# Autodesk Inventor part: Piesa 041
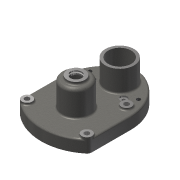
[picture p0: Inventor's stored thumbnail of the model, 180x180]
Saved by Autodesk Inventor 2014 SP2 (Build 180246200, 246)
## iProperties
Created: 2009-01
Part Number: Piesa 041
Document SubType Name: Modeling
Designer: Costel
Material: Steel, Cast
Density: 7.85 g/cm^3
Appearance: Steel - Cast
Author: Costel
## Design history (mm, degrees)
sketch "Sketch1"
  geometry: L1 (0, -196.304)-(0, 82.999) reference; L2 (-114.665, 0)-(114.665, 0) reference; L3 (-69.5, -125)-(-69.5, -47.789); L4 (69.5, -125)-(69.5, -47.789); A1 r 38 centre (0, 0) between (14.981, 34.922) and (-14.981, 34.922); A2 r 103.404 centre (0, -53) between (-65.87, -132.708) and (65.87, -132.708); A3 r 90 centre (20.5, -47.789) between (-14.981, 34.922) and (-69.5, -47.789); A4 r 90 centre (-20.5, -47.789) between (69.5, -47.789) and (14.981, 34.922); A5 r 10 centre (-59.5, -125) between (-69.5, -125) and (-65.87, -132.708); A6 r 10 centre (59.5, -125) between (65.87, -132.708) and (69.5, -125)
  constraints: 12 point on circle, 6 centre point, 6 tangent, 4 end point, 3 symmetric about line, 2 parallel, 2 point on line, 1 equal radius, 1 midpoint, 2 other
  dimensions: "d0" = 76 diameter of A1; "d1" = 53 distance of A1.centre A2.centre; "d5" = 139 distance between parallel lines of L4 L3; "d6" = 10 radius of A5; "d7" = 90 radius of A3; "d87" = 125 vertical distance of A5.centre A1.centre
extrude "Extrusion1" new body sketch "Sketch1" distance "d8" = 24; taper "d9" = 0 deg
sketch "Sketch2"
  geometry: L1 (0, -187)-(0, 75.5) reference; A1 r 38 centre (0, 0) between (14.981, 34.922) and (-14.981, 34.922) reference; A2 r 32 centre (0, 0) between (24.222, -20.911) and (-24.222, -20.911); A3 r 62.5 centre (0, -87) between (-26.245, -30.277) and (26.245, -30.277); A4 r 6 centre (-28.764, -24.832) between (-26.245, -30.277) and (-24.222, -20.911); A5 r 6 centre (28.764, -24.832) between (24.222, -20.911) and (26.245, -30.277)
  constraints: 8 point on circle, 4 centre point, 4 tangent, 1 coincident, 1 equal radius, 1 point on line
  dimensions: "d10" = 64 diameter of A2; "d11" = 87 distance of A1.centre A3.centre; "d12" = 125 diameter of A3; "d13" = 6 radius of A4
extrude "Extrusion2" cut sketch "Sketch2" distance "d14" = 18; taper "d15" = 0 deg
sketch "Sketch3"
  geometry: L1 (0, -195.284)-(0, 76.881) reference; L2 (-142.964, 0)-(175.456, 0) reference; L3 (-97.476, -11)-(129.968, -11); 2 further points
  constraints: 2 end point, 1 parallel, 1 point on line, 1 symmetric about line
  dimensions: "d16" = 11 distance between parallel lines of L2 L3; "d17" = 97 distance of point (48.5, -11) point (-48.5, -11)
hole "Hole1" sketch "Sketch3" at (-48.5, -11), (48.5, -11) diameter "d18" = 7.647; stored, may be unused: countersink angle "d22" = 90 deg, drill point angle "d24" = 118 deg; dims "d19" = 6, "d20" = 4, "d21" = 2, "d23" = 8
sketch "Sketch4"
  geometry: L1 (-142.964, 0)-(175.456, 0) reference; L2 (0, -195.284)-(0, 76.881) reference; L3 (-97.476, -24)-(129.968, -24); 2 further points
  constraints: 2 end point, 1 parallel, 1 point on line, 1 symmetric about line
  dimensions: "d25" = 24 distance between parallel lines of L1 L3; "d26" = 64 distance of point (32, -24) point (-32, -24)
hole "Hole2" sketch "Sketch4" at (-32, -24), (32, -24) diameter "d27" = 6.5; stored, may be unused: countersink angle "d31" = 90 deg, drill point angle "d33" = 118 deg; dims "d28" = 6, "d29" = 14, "d30" = 3, "d32" = 8
sketch "Sketch5"
  geometry: L1 (0, -195.284)-(0, 76.881) reference; L2 (-142.964, 0)-(175.456, 0) reference; L3 (-97.476, -35)-(129.968, -35); L4 (-97.476, -125)-(129.968, -125); C1 r 10 at (-59.5, -125); C2 r 10 at (-48.5, -35); C3 r 10 at (48.5, -35); C4 r 10 at (59.5, -125)
  constraints: 4 centre point, 4 end point, 2 parallel, 2 point on line, 2 symmetric about line, 1 equal radius, 2 other
  dimensions: "d34" = 35 distance between parallel lines of L2 L3; "d35" = 125 distance between parallel lines of L2 L4; "d36" = 20 diameter of C1; "d81" = 97 distance of C3.centre C2.centre; "d82" = 119 distance of C4.centre C1.centre
extrude "Extrusion3" join sketch "Sketch5" distance "d37" = 4; taper "d38" = 0 deg
sketch "Sketch6"
  geometry: C1 r 10 at (0, 0) reference; C2 r 10 at (-11, -90) reference; C3 r 10 at (108, -90) reference; C4 r 10 at (97, 0) reference; 4 further points
  constraints: 4 coincident
hole "Hole3" sketch "Sketch6" at (0, 0), (-11, -90), (108, -90), (97, 0) diameter "d39" = 10; stored, may be unused: countersink angle "d43" = 90 deg, drill point angle "d45" = 118 deg; dims "d40" = 6, "d41" = 14, "d42" = 3, "d44" = 8
sketch "Sketch7"
  geometry: L1 (-97.3, 0)-(97.3, 0) reference; L2 (0, -195.284)-(0, 76.881) reference; C1 r 28.5 at (0, 0)
  constraints: 1 centre point, 1 midpoint, 1 point on line
  dimensions: "d46" = 57 diameter of C1
extrude "Extrusion4" join sketch "Sketch7" distance "d47" = 43; taper "d48" = 0 deg
hole "Hole4" diameter "d51" = 46; stored, may be unused: countersink angle "d55" = 90 deg, drill point angle "d57" = 118 deg; dims "d49" = 10, "d50" = 10, "d52" = 6, "d53" = 14, "d54" = 3, "d56" = 8
sketch "Sketch8"
  geometry: L1 (0, -25.46)-(0, 105.86) reference; L2 (-87, -6.7)-(-87, 87.1); L3 (-104.5, 80)-(-87, 80); L4 (-87, 80)-(-87, 24); L5 (-87, 24)-(-115, 24); L6 (-115, 24)-(-115, 69); L7 (-125, 24)-(-47.789, 24) reference; L8 (-30.277, 0)-(-120.108, 0) reference; L9 (-104.5, 80)-(-104.5, 75); L10 (-104.5, 75)-(-109, 75); A1 r 6 centre (-109, 69) between (-109, 75) and (-115, 69)
  constraints: 14 end point, 3 parallel, 3 perpendicular, 2 collinear, 2 point on circle, 2 tangent, 1 centre point, 1 horizontal
  dimensions: "d58" = 87 distance between parallel lines of L1 L2; "d59" = 56 diameter of L6 L2; "d60" = 80 distance between parallel lines of L8 L3; "d61" = 35 diameter of L9 L2; "d62" = 75 distance between parallel lines of L8 L10; "d63" = 6 radius of A1
revolve "Revolution1" sketch "Sketch8" stored, may be unused: angle "d64" = 90 deg
workaxis "Work Axis1"
sketch "Sketch10"
  geometry: L1 (-87, -16)-(-87, 96) reference; L2 (-87, 18)-(-110, 18); L3 (-110, 18)-(-110, 66); L4 (-87, 80)-(-87, 18); L5 (-30.277, 0)-(-30.277, 0) reference; L6 (-30.277, 0)-(-30.277, 18) reference; L7 (-30.277, 18)-(-30.277, 18) reference; L8 (-110, 66)-(-110.5, 66); L9 (-110.5, 66)-(-110.5, 69); L10 (-110.5, 69)-(-104.5, 69); L11 (-104.5, 69)-(-104.5, 72); L12 (-104.5, 72)-(-98.25, 72); L13 (-98.25, 72)-(-98.25, 75.04); L14 (-98.25, 75.04)-(-102, 75.5); L15 (-102, 75.5)-(-102, 77.2); L16 (-102, 77.2)-(-98.25, 77.66); L17 (-98.25, 77.66)-(-98.25, 80); L18 (-98.25, 80)-(-87, 80); L19 (-69.5, 80)-(-104.5, 80) reference; L20 (-102, 76.35)-(-87, 76.35); L21 (-30.277, 0)-(-30.277, 18) reference
  constraints: 30 end point, 9 parallel, 4 collinear, 3 perpendicular, 2 point on line, 1 horizontal, 1 midpoint, 1 other
  dimensions: "d65" = 4.5 distance from line of L19 L14.end; "d66" = 14 deg angle of L16 L14; "d67" = 22.5 diameter of L17 L1; "d68" = 30 diameter of L15 L1; "d70" = 72 distance between parallel lines of L5 L12; "d71" = 3 distance between parallel lines of L8 L10; "d72" = 69 distance between parallel lines of L5 L10; "d73" = 47 diameter of L9 L1; "d74" = 46 diameter of L3 L1; "d79" = 35 diameter of L11 L1; "d83" = 2.8 distance from line of L19 L15.end
revolve "Revolution2" sketch "Sketch10" stored, may be unused: angle "d80" = 90 deg
fillet "Fillet3" dims "d86" = 3
fillet "Fillet4" dims "d88" = 3
body "Solid1"
node "Projected Loop1"
node "Projected Loop2"
